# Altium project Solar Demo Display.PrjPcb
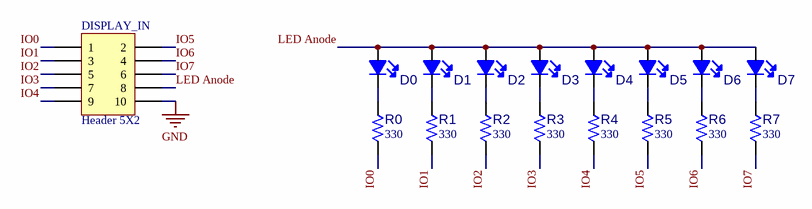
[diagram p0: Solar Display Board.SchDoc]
ProjectDrawnBy: **; ProjectEngineer: **; ProjectPartNumber: **; ProjectPCBAssyNumber: **; ProjectPCBNumber: **; ProjectRevisionART: **; ProjectRevisionASSY: **; ProjectRevisionFAB: **; ProjectRevisionSCH: **; ProjectTitle: **
1 sheet, 17 parts. Net scope: global (net labels, ports and power ports of the same name join across sheets).
Board file: Solar Display Board.PcbDoc

## Sheet Solar Display Board.SchDoc
size B; CompanyName: Microchip Technology Inc.; Organization: Microchip Technology; Address1: 2355 West Chandler Blvd.; Address2: Chandler, AZ  85224; Address4: USA; SheetNumber: 1; SheetTotal: 1; SheetTitle: **

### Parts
D0  LED  [0805 for LED]  (value not drawn)
D1  LED  [0805 for LED]  (value not drawn)
D2  LED  [0805 for LED]  (value not drawn)
D3  LED  [0805 for LED]  (value not drawn)
D4  LED  [0805 for LED]  (value not drawn)
D5  LED  [0805 for LED]  (value not drawn)
D6  LED  [0805 for LED]  (value not drawn)
D7  LED  [0805 for LED]  (value not drawn)
DISPLAY_IN  Header 5X2  [HDR2X5]
R0  value 330  [0805]  (hidden comment: Resistor)
R1  value 330  [0805]  (hidden comment: Resistor)
R2  value 330  [0805]  (hidden comment: Resistor)
R3  value 330  [0805]  (hidden comment: Resistor)
R4  value 330  [0805]  (hidden comment: Resistor)
R5  value 330  [0805]  (hidden comment: Resistor)
R6  value 330  [0805]  (hidden comment: Resistor)
R7  value 330  [0805]  (hidden comment: Resistor)

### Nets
GND: DISPLAY_IN.10
IO0: DISPLAY_IN.1 R0.1
IO1: DISPLAY_IN.3 R1.1
IO2: DISPLAY_IN.5 R2.1
IO3: DISPLAY_IN.7 R3.1
IO4: DISPLAY_IN.9 R4.1
IO5: DISPLAY_IN.2 R5.1
IO6: DISPLAY_IN.4 R6.1
IO7: DISPLAY_IN.6 R7.1
LED Anode: D0.A(Anode) D1.A(Anode) D2.A(Anode) D3.A(Anode) D4.A(Anode) D5.A(Anode) D6.A(Anode) D7.A(Anode) DISPLAY_IN.8
NetD0_K: D0.K(Cathode) R0.2
NetD1_K: D1.K(Cathode) R1.2
NetD2_K: D2.K(Cathode) R2.2
NetD3_K: D3.K(Cathode) R3.2
NetD4_K: D4.K(Cathode) R4.2
NetD5_K: D5.K(Cathode) R5.2
NetD6_K: D6.K(Cathode) R6.2
NetD7_K: D7.K(Cathode) R7.2

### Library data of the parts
D0-D2 = LED: LED Color: Green
D3-D5 = LED: LED Color: Yellow
D6 D7 = LED: LED Color: Red
DISPLAY_IN = Header 5X2: Header, 5-Pin, Dual row; System: Connector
